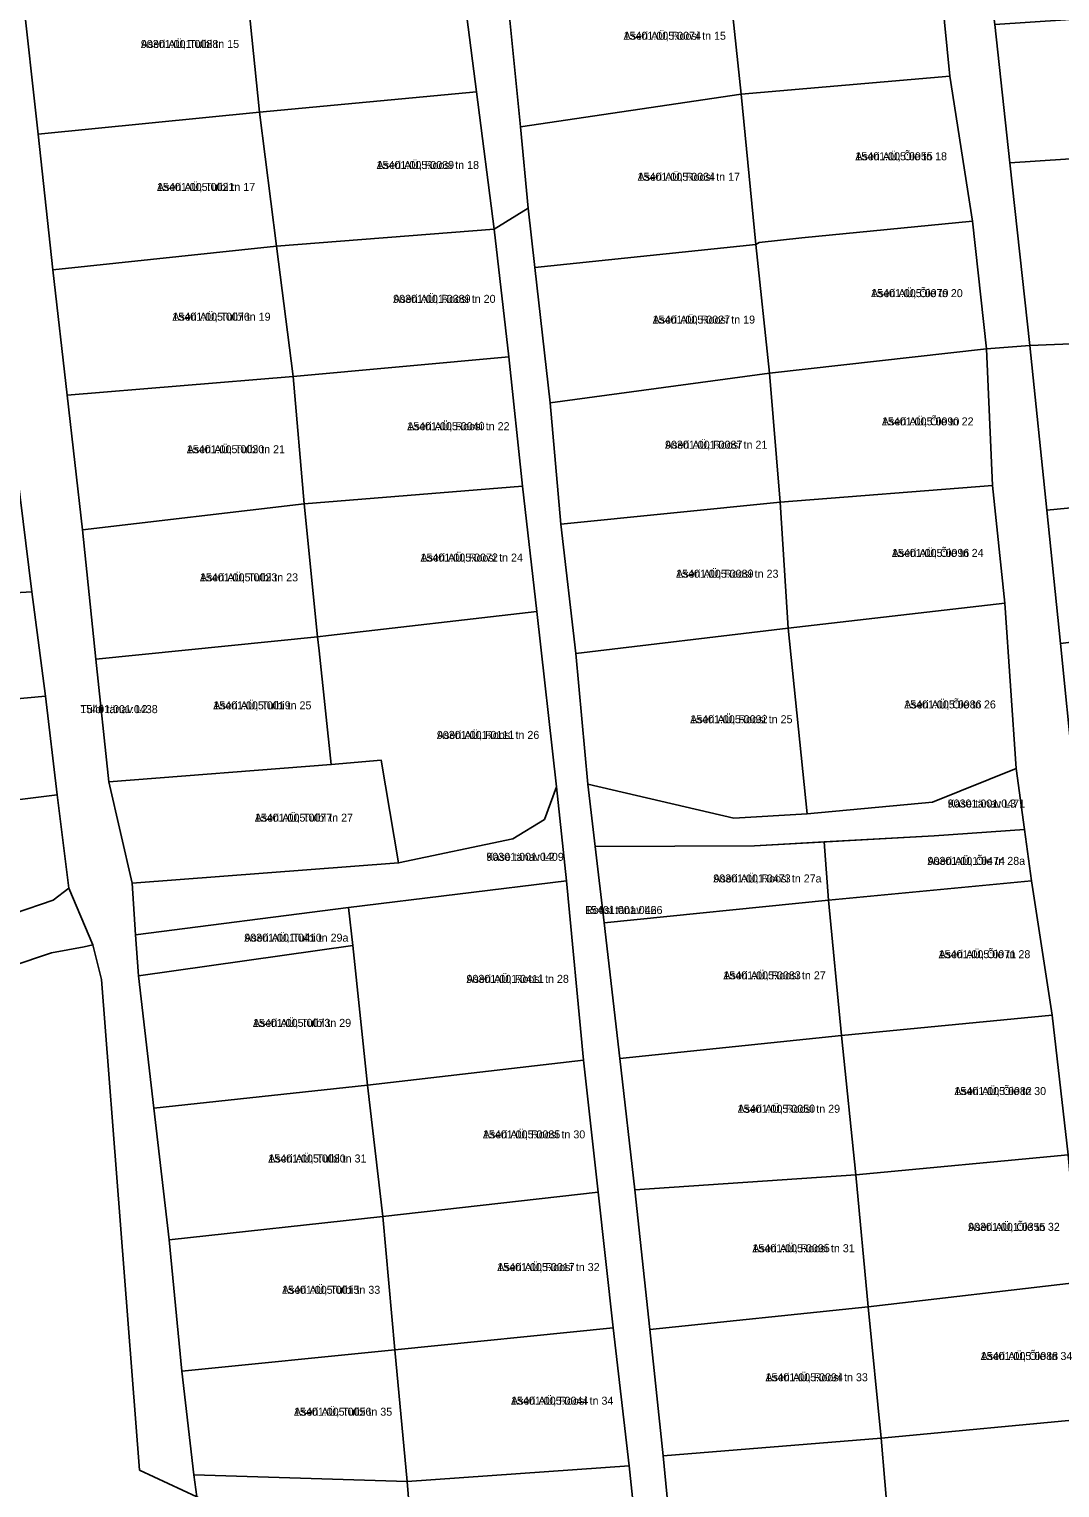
# Model space of a CAD drawing. Extents: x 634518 to 667988, y 6584667 to 6604739.
# Drawn here: x 663294.1 to 663487.1, y 6593164.3 to 6593437.7 of the extents above; entities that cross this region are included whole.
import ezdxf

# ---------------------------------------------------------------- set-up
doc = ezdxf.new("R2010")
doc.units = 0
for name, color, linetype in [('L_AADRESS', 7, 'Continuous'), ('PIIR', 7, 'Continuous'), ('TUNNUS', 7, 'Continuous')]:
    doc.layers.add(name, color=color, linetype=linetype)

msp = doc.modelspace()

# ---------------------------------------------------------------- linework, layer by layer
at = {"layer": 'PIIR'}
for points in [[(663347.27, 6593688.66), (663356.84, 6593683.81), (663357.71, 6593669.46), (663365.34, 6593616.35), (663367.78, 6593592.98), (663370.62, 6593567.19), (663373.25, 6593544.18), (663375.95, 6593520.78), (663378.81, 6593497.26), (663381.34, 6593472.32), (663383.16, 6593448.81), (663386.13, 6593419.38), (663387.58, 6593404.14), (663381.19, 6593400.18), (663377.9, 6593425.95), (663374.25, 6593454.09), (663371.75, 6593479.44), (663369.06, 6593504.56), (663366.37, 6593529.21), (663363.79, 6593552.89), (663360.9, 6593577.14)], [(663444.92, 6593634.82), (663457.15, 6593627.47), (663456.84, 6593618.96), (663461.53, 6593562.08), (663464.08, 6593537.29), (663467.07, 6593512.64), (663469.3, 6593487.56), (663471.91, 6593462.82), (663474.98, 6593438.56), (663477.8, 6593412.62), (663481.51, 6593378.39), (663473.37, 6593377.76), (663470.8, 6593401.71), (663466.55, 6593428.87), (663463.58, 6593458.67), (663462.1, 6593481.86), (663459.51, 6593505.25), (663457, 6593529.47), (663454.83, 6593552.74), (663452.05, 6593577.43), (663448.85, 6593601.76), (663446.33, 6593625.89)], [(663427.43, 6593425.5), (663424.64, 6593452), (663463.58, 6593458.67), (663466.55, 6593428.87)], [(663374.25, 6593454.09), (663377.9, 6593425.95), (663337.26, 6593422.12), (663334.36, 6593450.29)], [(663386.13, 6593419.38), (663383.16, 6593448.81), (663403.42, 6593450.56), (663424.64, 6593452), (663427.43, 6593425.5)], [(663334.36, 6593450.29), (663337.26, 6593422.12), (663295.8, 6593418.01), (663292.72, 6593445.68)], [(663515.6, 6593441.25), (663518.55, 6593415.33), (663477.8, 6593412.62), (663474.98, 6593438.56)], [(663427.43, 6593425.5), (663466.55, 6593428.87), (663470.8, 6593401.71), (663438.83, 6593398.57), (663430.79, 6593397.66), (663430.17, 6593397.32)], [(663377.9, 6593425.95), (663381.19, 6593400.18), (663340.42, 6593396.99), (663337.26, 6593422.12)], [(663386.13, 6593419.38), (663427.43, 6593425.5), (663430.17, 6593397.32), (663388.77, 6593393.02), (663387.58, 6593404.14)], [(663337.26, 6593422.12), (663340.42, 6593396.99), (663298.53, 6593392.58), (663295.8, 6593418.01)], [(663518.55, 6593415.33), (663523.16, 6593380.1), (663481.51, 6593378.39), (663477.8, 6593412.62)], [(663381.19, 6593400.18), (663387.58, 6593404.14), (663388.77, 6593393.02), (663391.65, 6593367.66), (663393.68, 6593344.89), (663396.51, 6593320.66), (663398.75, 6593296.18), (663400.11, 6593284.48), (663401.77, 6593270.18), (663404.7, 6593244.75), (663407.53, 6593220.11), (663410.33, 6593193.95), (663412.81, 6593170.28), (663415.24, 6593145.66), (663408.9, 6593145.21), (663406.48, 6593168.39), (663403.48, 6593194.27), (663400.64, 6593219.67), (663397.91, 6593244.42), (663394.71, 6593278.08), (663392.83, 6593295.68), (663389.16, 6593328.51), (663386.48, 6593351.99), (663383.92, 6593376.29)], [(663438.83, 6593398.57), (663470.8, 6593401.71), (663473.37, 6593377.76), (663432.78, 6593373.18), (663430.17, 6593397.32), (663430.79, 6593397.66)], [(663383.92, 6593376.29), (663343.54, 6593372.58), (663340.42, 6593396.99), (663381.19, 6593400.18)], [(663301.21, 6593369.07), (663298.53, 6593392.58), (663340.42, 6593396.99), (663343.54, 6593372.58)], [(663430.17, 6593397.32), (663432.78, 6593373.18), (663391.65, 6593367.66), (663388.77, 6593393.02)], [(663523.16, 6593380.1), (663525.97, 6593351.51), (663484.73, 6593347.53), (663481.51, 6593378.39)], [(663434.77, 6593349.05), (663432.78, 6593373.18), (663473.37, 6593377.76), (663474.54, 6593352.15)], [(663383.92, 6593376.29), (663386.48, 6593351.99), (663345.6, 6593348.73), (663343.54, 6593372.58)], [(663301.21, 6593369.07), (663343.54, 6593372.58), (663345.6, 6593348.73), (663304.06, 6593343.81)], [(663393.68, 6593344.89), (663391.65, 6593367.66), (663432.78, 6593373.18), (663434.77, 6593349.05)], [(663236.72, 6593348.86), (663291.86, 6593354.5), (663294.58, 6593332.19), (663238.81, 6593328.98)], [(663348.1, 6593323.79), (663345.6, 6593348.73), (663386.48, 6593351.99), (663389.16, 6593328.51), (663350.18, 6593324.03)], [(663434.77, 6593349.05), (663474.54, 6593352.15), (663476.85, 6593330.09), (663436.26, 6593325.38)], [(663525.97, 6593351.51), (663528.36, 6593327.67), (663487.23, 6593322.53), (663484.73, 6593347.53)], [(663304.06, 6593343.81), (663345.6, 6593348.73), (663348.1, 6593323.79), (663306.56, 6593319.62)], [(663393.68, 6593344.89), (663434.77, 6593349.05), (663436.26, 6593325.38), (663396.51, 6593320.66)], [(663238.81, 6593328.98), (663294.58, 6593332.19), (663297.12, 6593312.69), (663241.26, 6593307.46)], [(663348.39, 6593321.13), (663348.1, 6593323.79), (663350.18, 6593324.03), (663389.16, 6593328.51), (663392.83, 6593295.68), (663390.6, 6593289.55), (663384.66, 6593285.94), (663363.27, 6593281.41), (663360.02, 6593300.64), (663350.66, 6593299.84)], [(663439.79, 6593290.62), (663436.26, 6593325.38), (663476.85, 6593330.09), (663478.94, 6593299.1), (663463.31, 6593292.82)], [(663396.51, 6593320.66), (663436.26, 6593325.38), (663439.79, 6593290.62), (663426.09, 6593289.81), (663398.75, 6593296.18)], [(663348.1, 6593323.79), (663348.39, 6593321.13), (663350.66, 6593299.84), (663309.02, 6593296.59), (663306.56, 6593319.62)], [(663241.26, 6593307.46), (663297.12, 6593312.69), (663299.31, 6593294.15), (663243.51, 6593287.2)], [(663313.37, 6593277.64), (663309.02, 6593296.59), (663350.66, 6593299.84), (663360.02, 6593300.64), (663363.27, 6593281.41)], [(663398.75, 6593296.18), (663426.09, 6593289.81), (663439.79, 6593290.62), (663463.31, 6593292.82), (663478.94, 6593299.1), (663480.5, 6593287.65), (663463.62, 6593286.47), (663429.95, 6593284.61), (663400.11, 6593284.48)], [(663394.71, 6593278.08), (663353.91, 6593273.06), (663314.03, 6593267.93), (663313.37, 6593277.64), (663363.27, 6593281.41), (663384.66, 6593285.94), (663390.6, 6593289.55), (663392.83, 6593295.68)], [(663243.51, 6593287.2), (663299.31, 6593294.15), (663301.52, 6593276.65), (663298.58, 6593274.43), (663247.41, 6593256.96)], [(663442.98, 6593285.33), (663463.62, 6593286.47), (663480.5, 6593287.65), (663481.81, 6593278.04), (663443.81, 6593274.42)], [(663400.11, 6593284.48), (663429.95, 6593284.61), (663442.98, 6593285.33), (663443.81, 6593274.42), (663401.77, 6593270.18)], [(663051.92, 6593221.69), (663058.85, 6593222.49), (663096.51, 6593227.16), (663139.66, 6593233.48), (663151.82, 6593235.53), (663192.45, 6593240.67), (663236.02, 6593247.4), (663237.33, 6593250.38), (663247.41, 6593256.96), (663298.58, 6593274.43), (663301.52, 6593276.65), (663306, 6593266.08), (663304.39, 6593265.7), (663298.27, 6593264.58), (663290.65, 6593262), (663252.5, 6593243.18), (663243.54, 6593239.44), (663242.91, 6593239.18), (663215.16, 6593233.28), (663102.17, 6593217.97), (663087.61, 6593215.97), (663065.09, 6593212.94), (663053.47, 6593211.36), (663052.77, 6593215.74)], [(663397.91, 6593244.42), (663357.48, 6593239.78), (663354.73, 6593265.9), (663353.91, 6593273.06), (663394.71, 6593278.08)], [(663446.23, 6593249.06), (663443.81, 6593274.42), (663481.81, 6593278.04), (663485.68, 6593252.87)], [(663314.03, 6593267.93), (663353.91, 6593273.06), (663354.73, 6593265.9), (663314.57, 6593260.23)], [(663404.7, 6593244.75), (663401.77, 6593270.18), (663443.81, 6593274.42), (663446.23, 6593249.06)], [(663307.64, 6593259.58), (663314.76, 6593167.62), (663325.51, 6593162.57), (663353.9, 6593149.24), (663341.95, 6593101.12), (663283.08, 6593101.01), (663025.91, 6593100.09), (663077.08, 6593196.44), (663087.61, 6593215.97), (663102.17, 6593217.97), (663215.16, 6593233.28), (663242.91, 6593239.18), (663243.54, 6593239.44), (663252.5, 6593243.18), (663290.65, 6593262), (663298.27, 6593264.58), (663304.39, 6593265.7), (663306, 6593266.08)], [(663317.41, 6593235.46), (663314.57, 6593260.23), (663354.73, 6593265.9), (663357.48, 6593239.78)], [(663488.67, 6593226.67), (663448.93, 6593222.93), (663446.23, 6593249.06), (663485.68, 6593252.87)], [(663446.23, 6593249.06), (663448.93, 6593222.93), (663407.53, 6593220.11), (663404.7, 6593244.75)], [(663360.3, 6593215.14), (663357.48, 6593239.78), (663397.91, 6593244.42), (663400.64, 6593219.67)], [(663320.3, 6593210.74), (663317.41, 6593235.46), (663357.48, 6593239.78), (663360.3, 6593215.14)], [(663488.67, 6593226.67), (663490.91, 6593202.86), (663451.26, 6593198.23), (663448.93, 6593222.93)], [(663407.53, 6593220.11), (663448.93, 6593222.93), (663451.26, 6593198.23), (663410.33, 6593193.95)], [(663360.3, 6593215.14), (663400.64, 6593219.67), (663403.48, 6593194.27), (663362.57, 6593190.14)], [(663360.3, 6593215.14), (663362.57, 6593190.14), (663322.7, 6593186.16), (663320.3, 6593210.74)], [(663451.26, 6593198.23), (663490.91, 6593202.86), (663493.44, 6593177.36), (663453.7, 6593173.62)], [(663410.33, 6593193.95), (663451.26, 6593198.23), (663453.7, 6593173.62), (663412.81, 6593170.28)], [(663362.57, 6593190.14), (663403.48, 6593194.27), (663406.48, 6593168.39), (663364.88, 6593165.47)], [(663322.7, 6593186.16), (663362.57, 6593190.14), (663364.88, 6593165.47), (663324.91, 6593166.71)], [(663456.2, 6593143.61), (663455.75, 6593149.21), (663453.7, 6593173.62), (663493.44, 6593177.36), (663497.75, 6593146.66)], [(663455.75, 6593149.21), (663415.24, 6593145.66), (663412.81, 6593170.28), (663453.7, 6593173.62)], [(663353.9, 6593149.24), (663325.51, 6593162.57), (663324.91, 6593166.71), (663364.88, 6593165.47), (663366.48, 6593145.41), (663366.71, 6593142.29)], [(663373.13, 6593142.64), (663366.48, 6593145.41), (663364.88, 6593165.47), (663406.48, 6593168.39), (663408.9, 6593145.21), (663376.24, 6593142.16)]]:
    msp.add_lwpolyline(points, close=True, dxfattribs=at)
for points in [[(663292.72, 6593445.68), (663295.8, 6593418.01), (663298.53, 6593392.58), (663301.21, 6593369.07), (663304.06, 6593343.81), (663306.56, 6593319.62), (663309.02, 6593296.59), (663313.37, 6593277.64), (663314.03, 6593267.93), (663314.57, 6593260.23), (663317.41, 6593235.46), (663320.3, 6593210.74), (663322.7, 6593186.16), (663324.91, 6593166.71), (663325.51, 6593162.57), (663314.76, 6593167.62), (663307.64, 6593259.58), (663306, 6593266.08), (663301.52, 6593276.65), (663299.31, 6593294.15), (663297.12, 6593312.69), (663294.58, 6593332.19), (663291.86, 6593354.5)], [(663497.75, 6593146.66), (663493.44, 6593177.36), (663490.91, 6593202.86), (663488.67, 6593226.67), (663485.68, 6593252.87), (663481.81, 6593278.04), (663480.5, 6593287.65), (663478.94, 6593299.1), (663476.85, 6593330.09), (663474.54, 6593352.15), (663473.37, 6593377.76), (663481.51, 6593378.39), (663484.73, 6593347.53), (663487.23, 6593322.53), (663489.7, 6593298.29), (663491.02, 6593288.46), (663492.03, 6593278.94), (663494.68, 6593254.15), (663497.19, 6593229.42), (663499.76, 6593204.01), (663502.29, 6593179.87), (663504.87, 6593154.31)]]:
    msp.add_lwpolyline(points, dxfattribs=at)

# ---------------------------------------------------------------- texts
at = {"layer": 'L_AADRESS'}
for s, p in [('Aseri AÜ, Roosi tn 15', (663405.42, 6593435.69)), ('Aseri AÜ, Tulbi tn 15', (663315.01, 6593434.15)), ('Aseri AÜ, Roosi tn 18', (663359.17, 6593411.47)), ('Aseri AÜ, Õie tn 18', (663448.83, 6593413.1)), ('Aseri AÜ, Roosi tn 17', (663408.05, 6593409.26)), ('Aseri AÜ, Tulbi tn 17', (663318.03, 6593407.35)), ('Aseri AÜ, Roosi tn 20', (663362.27, 6593386.38)), ('Aseri AÜ, Õie tn 20', (663451.78, 6593387.45)), ('Aseri AÜ, Tulbi tn 19', (663320.91, 6593383.03)), ('Aseri AÜ, Roosi tn 19', (663410.87, 6593382.49)), ('Aseri AÜ, Roosi tn 22', (663364.89, 6593362.51)), ('Aseri AÜ, Õie tn 22', (663453.81, 6593363.41)), ('Aseri AÜ, Roosi tn 21', (663413.18, 6593359.04)), ('Aseri AÜ, Tulbi tn 21', (663323.61, 6593358.19)), ('Aseri AÜ, Roosi tn 24', (663367.39, 6593337.89)), ('Aseri AÜ, Õie tn 24', (663455.68, 6593338.76)), ('Aseri AÜ, Tulbi tn 23', (663326.06, 6593334.18)), ('Aseri AÜ, Roosi tn 23', (663415.26, 6593334.86)), ('Aseri AÜ, Tulbi tn 25', (663328.56, 6593310.19)), ('Aseri AÜ, Õie tn 26', (663457.98, 6593310.36)), ('Tulbi tänav L2', (663303.66, 6593309.48)), ('Aseri AÜ, Roosi tn 25', (663417.89, 6593307.59)), ('Aseri AÜ, Roosi tn 26', (663370.46, 6593304.65)), ('Kase tänav L3', (663466.12, 6593291.79)), ('Aseri AÜ, Tulbi tn 27', (663336.35, 6593289.14)), ('Kase tänav L2', (663379.72, 6593281.8)), ('Aseri AÜ, Õie tn 28a', (663462.35, 6593281.04)), ('Aseri AÜ, Roosi tn 27a', (663422.22, 6593277.75)), ('Roosi tänav L2', (663398.21, 6593271.84)), ('Aseri AÜ, Tulbi tn 29a', (663334.38, 6593266.65)), ('Aseri AÜ, Õie tn 28', (663464.44, 6593263.55)), ('Aseri AÜ, Roosi tn 28', (663376, 6593258.93)), ('Aseri AÜ, Roosi tn 27', (663424.11, 6593259.59)), ('Aseri AÜ, Tulbi tn 29', (663336, 6593250.68)), ('Aseri AÜ, Õie tn 30', (663467.39, 6593237.9)), ('Aseri AÜ, Roosi tn 29', (663426.8, 6593234.58)), ('Aseri AÜ, Roosi tn 30', (663379.07, 6593229.78)), ('Aseri AÜ, Tulbi tn 31', (663338.87, 6593225.26)), ('Aseri AÜ, Õie tn 32', (663469.96, 6593212.45)), ('Aseri AÜ, Roosi tn 31', (663429.54, 6593208.44)), ('Aseri AÜ, Roosi tn 32', (663381.76, 6593204.91)), ('Aseri AÜ, Tulbi tn 33', (663341.45, 6593200.65)), ('Aseri AÜ, Õie tn 34', (663472.31, 6593188.24)), ('Aseri AÜ, Roosi tn 33', (663432, 6593184.26)), ('Aseri AÜ, Roosi tn 34', (663384.34, 6593179.87)), ('Aseri AÜ, Tulbi tn 35', (663343.69, 6593177.8))]:
    msp.add_text(s, height=1.5, dxfattribs=at).set_placement(p)
at = {"layer": 'TUNNUS'}
for s, p in [('15401:005:0074', (663405.42, 6593435.69)), ('90301:001:0088', (663315.01, 6593434.15)), ('15401:005:0039', (663359.17, 6593411.47)), ('15401:005:0055', (663448.83, 6593413.1)), ('15401:005:0034', (663408.05, 6593409.26)), ('15401:005:0021', (663318.03, 6593407.35)), ('90301:001:0389', (663362.27, 6593386.38)), ('15401:005:0079', (663451.78, 6593387.45)), ('15401:005:0076', (663320.91, 6593383.03)), ('15401:005:0027', (663410.87, 6593382.49)), ('15401:005:0040', (663364.89, 6593362.51)), ('15401:005:0090', (663453.81, 6593363.41)), ('90301:001:0087', (663413.18, 6593359.04)), ('15401:005:0030', (663323.61, 6593358.19)), ('15401:005:0072', (663367.39, 6593337.89)), ('15401:005:0096', (663455.68, 6593338.76)), ('15401:005:0089', (663415.26, 6593334.86)), ('15401:005:0023', (663326.06, 6593334.18)), ('15401:005:0019', (663328.56, 6593310.19)), ('15401:005:0086', (663457.98, 6593310.36)), ('15401:001:0438', (663303.66, 6593309.48)), ('15401:005:0092', (663417.89, 6593307.59)), ('90301:001:0111', (663370.46, 6593304.65)), ('90301:001:0471', (663466.12, 6593291.79)), ('15401:005:0077', (663336.35, 6593289.14)), ('90301:001:0409', (663379.72, 6593281.8)), ('90301:001:0474', (663462.35, 6593281.04)), ('90301:001:0473', (663422.22, 6593277.75)), ('15401:001:0466', (663398.21, 6593271.84)), ('90301:001:0410', (663334.38, 6593266.65)), ('15401:005:0071', (663464.44, 6593263.55)), ('90301:001:0411', (663376, 6593258.93)), ('15401:005:0083', (663424.11, 6593259.59)), ('15401:005:0073', (663336, 6593250.68)), ('15401:005:0082', (663467.39, 6593237.9)), ('15401:005:0050', (663426.8, 6593234.58)), ('15401:005:0085', (663379.07, 6593229.78)), ('15401:005:0080', (663338.87, 6593225.26)), ('90301:001:0355', (663469.96, 6593212.45)), ('15401:005:0095', (663429.54, 6593208.44)), ('15401:005:0017', (663381.76, 6593204.91)), ('15401:005:0015', (663341.45, 6593200.65)), ('15401:005:0088', (663472.31, 6593188.24)), ('15401:005:0094', (663432, 6593184.26)), ('15401:005:0044', (663384.34, 6593179.87)), ('15401:005:0056', (663343.69, 6593177.8))]:
    msp.add_text(s, height=1.5, dxfattribs=at).set_placement(p)

doc.saveas('drawing.dxf')
